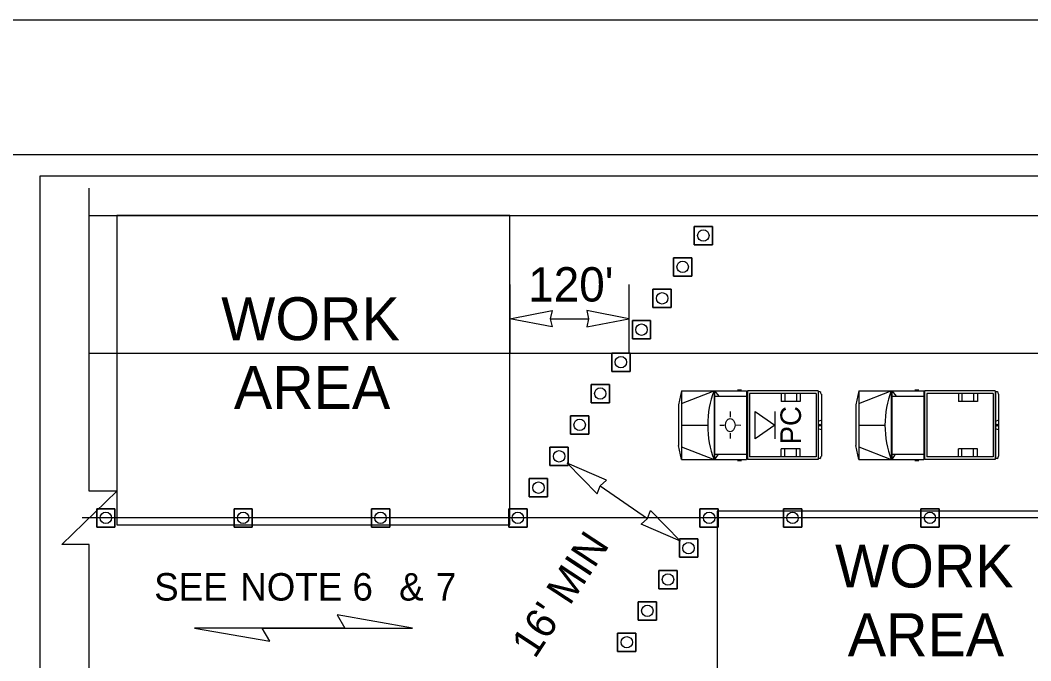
# Model space of a CAD drawing. Extents: x 99999.1 to 100095.7, y 99995 to 100010.7.
# Drawn here: x 100045.223 to 100047.578, y 100009.196 to 100010.687 of the extents above; entities that cross this region are included whole.
import ezdxf

# ---------------------------------------------------------------- set-up
doc = ezdxf.new("R2010")
doc.units = 0
for name, color, linetype in [('RD_ED_ShoulderPavedEdge', 7, 'Continuous'), ('RD_MK_LineEdgeWhite', 7, 'Continuous'), ('RD_MK_LineSkipCenter', 7, 'Continuous'), ('SH_GI_PlotLimits', 7, 'Continuous'), ('SH_GI_SheetBorder', 7, 'Continuous'), ('SH_TI_Tables', 7, 'Continuous'), ('TR_WZ_MotoristVehicle', 7, 'Continuous'), ('TR_WZ_PortableSignMountBlk-Wht', 7, 'Continuous'), ('TR_WZ_TrafficCone', 7, 'Continuous'), ('TR_WZ_WorkAreaLabel', 7, 'Continuous'), ('TR_WZ_WorkZoneDetails', 7, 'Continuous'), ('TR_WZ_WorkZoneTextCurrent', 7, 'Continuous')]:
    doc.layers.add(name, color=color, linetype=linetype)

msp = doc.modelspace()

# ---------------------------------------------------------------- linework, layer by layer
at = {"layer": 'RD_ED_ShoulderPavedEdge'}
msp.add_line((100045.3842, 100010.2323), (100049.3016, 100010.2323), dxfattribs=at)
at = {"layer": 'RD_MK_LineEdgeWhite'}
msp.add_line((100045.3842, 100009.9123), (100049.3016, 100009.9123), dxfattribs=at)
at = {"layer": 'RD_MK_LineSkipCenter'}
msp.add_lwpolyline([(100049.285, 100009.5283), (100045.3677, 100009.5283)], dxfattribs=at)
at = {"layer": 'SH_GI_PlotLimits'}
msp.add_lwpolyline([(100039.0625, 99999.6875), (100056.0625, 99999.6875), (100056.0625, 100010.6875), (100039.0625, 100010.6875)], close=True, dxfattribs=at)
at = {"layer": 'SH_GI_SheetBorder'}
msp.add_line((100040, 100010.375), (100055.75, 100010.375), dxfattribs=at)
at = {"layer": 'SH_TI_Tables'}
msp.add_lwpolyline([(100045.2702, 100010.325), (100050.7241, 100010.325), (100050.7241, 100008.2892), (100045.2702, 100008.2892)], close=True, dxfattribs=at)
at = {"layer": 'TR_WZ_MotoristVehicle'}
for p, q in [((100046.7643, 100009.8243), (100046.7569, 100009.792)), ((100046.7643, 100009.8243), (100046.7643, 100009.6643)), ((100046.7643, 100009.8243), (100046.9154, 100009.8243)), ((100046.7643, 100009.795), (100046.8399, 100009.8243)), ((100046.8399, 100009.8243), (100046.8399, 100009.6643)), ((100046.8412, 100009.8243), (100046.8412, 100009.6643)), ((100046.8412, 100009.8243), (100046.8509, 100009.8119)), ((100046.8412, 100009.8119), (100046.9154, 100009.8119)), ((100046.8948, 100009.8266), (100046.9039, 100009.8266)), ((100046.9154, 100009.8243), (100046.9154, 100009.6643)), ((100047.0822, 100009.8243), (100046.9176, 100009.8243)), ((100046.9176, 100009.8243), (100046.9176, 100009.6643)), ((100047.0775, 100009.8179), (100046.9223, 100009.8179)), ((100046.9223, 100009.8179), (100046.9223, 100009.6707)), ((100046.9965, 100009.8179), (100046.9965, 100009.7995)), ((100047.0045, 100009.8179), (100047.0045, 100009.7995)), ((100047.0317, 100009.8179), (100047.0317, 100009.7995)), ((100047.0404, 100009.8179), (100047.0404, 100009.7995)), ((100047.0775, 100009.8179), (100047.0775, 100009.6707)), ((100047.0822, 100009.8243), (100047.0822, 100009.6643)), ((100047.0863, 100009.8217), (100047.0828, 100009.8217)), ((100047.0828, 100009.8217), (100047.0828, 100009.667)), ((100047.0899, 100009.8168), (100047.0899, 100009.6718)), ((100047.1773, 100009.8243), (100047.1699, 100009.792)), ((100047.1773, 100009.8243), (100047.1773, 100009.6643)), ((100047.1773, 100009.8243), (100047.3284, 100009.8243)), ((100047.1773, 100009.795), (100047.2529, 100009.8243)), ((100047.2529, 100009.8243), (100047.2529, 100009.6643)), ((100047.2543, 100009.8243), (100047.2543, 100009.6643)), ((100047.2543, 100009.8243), (100047.2639, 100009.8119)), ((100047.2543, 100009.8119), (100047.3284, 100009.8119)), ((100047.3078, 100009.8266), (100047.3169, 100009.8266)), ((100047.3284, 100009.8243), (100047.3284, 100009.6643)), ((100047.4952, 100009.8243), (100047.3306, 100009.8243)), ((100047.3306, 100009.8243), (100047.3306, 100009.6643)), ((100047.4905, 100009.8179), (100047.3353, 100009.8179)), ((100047.3353, 100009.8179), (100047.3353, 100009.6707)), ((100047.4095, 100009.8179), (100047.4095, 100009.7995)), ((100047.4175, 100009.8179), (100047.4175, 100009.7995)), ((100047.4447, 100009.8179), (100047.4447, 100009.7995)), ((100047.4535, 100009.8179), (100047.4535, 100009.7995)), ((100047.4905, 100009.8179), (100047.4905, 100009.6707)), ((100047.4952, 100009.8243), (100047.4952, 100009.6643)), ((100047.4993, 100009.8217), (100047.4958, 100009.8217)), ((100047.4958, 100009.8217), (100047.4958, 100009.667)), ((100047.5029, 100009.8168), (100047.5029, 100009.6718)), ((100046.7569, 100009.792), (100046.7569, 100009.6966)), ((100047.0404, 100009.7995), (100046.9965, 100009.7995)), ((100047.1699, 100009.792), (100047.1699, 100009.6966)), ((100047.4535, 100009.7995), (100047.4095, 100009.7995)), ((100046.8775, 100009.776), (100046.8775, 100009.7631)), ((100046.7643, 100009.7443), (100046.825, 100009.7443)), ((100046.8534, 100009.7444), (100046.8635, 100009.7444)), ((100046.8888, 100009.7441), (100046.8888, 100009.7441)), ((100046.9022, 100009.7437), (100046.8903, 100009.744)), ((100047.0899, 100009.7556), (100047.0828, 100009.7526)), ((100047.0899, 100009.7331), (100047.0828, 100009.7361)), ((100047.088, 100009.7443), (100047.0847, 100009.7443)), ((100047.0863, 100009.7466), (100047.0863, 100009.7421)), ((100047.1773, 100009.7443), (100047.238, 100009.7443)), ((100047.5029, 100009.7556), (100047.4958, 100009.7526)), ((100047.5029, 100009.7331), (100047.4958, 100009.7361)), ((100047.501, 100009.7443), (100047.4977, 100009.7443)), ((100047.4993, 100009.7466), (100047.4993, 100009.7421)), ((100046.8781, 100009.7136), (100046.8779, 100009.7256)), ((100046.7643, 100009.6643), (100046.7569, 100009.6966)), ((100046.7643, 100009.6936), (100046.8399, 100009.6643)), ((100046.9965, 100009.6707), (100046.9965, 100009.6891)), ((100047.0404, 100009.6891), (100046.9965, 100009.6891)), ((100047.0045, 100009.6707), (100047.0045, 100009.6891)), ((100047.0317, 100009.6707), (100047.0317, 100009.6891)), ((100047.0404, 100009.6707), (100047.0404, 100009.6891)), ((100047.1773, 100009.6643), (100047.1699, 100009.6966)), ((100047.1773, 100009.6936), (100047.2529, 100009.6643)), ((100047.4095, 100009.6707), (100047.4095, 100009.6891)), ((100047.4535, 100009.6891), (100047.4095, 100009.6891)), ((100047.4175, 100009.6707), (100047.4175, 100009.6891)), ((100047.4447, 100009.6707), (100047.4447, 100009.6891)), ((100047.4535, 100009.6707), (100047.4535, 100009.6891)), ((100046.8412, 100009.6767), (100046.9154, 100009.6767)), ((100046.8492, 100009.6767), (100046.8412, 100009.6643)), ((100047.0775, 100009.6707), (100046.9223, 100009.6707)), ((100047.0863, 100009.667), (100047.0828, 100009.667)), ((100047.2543, 100009.6767), (100047.3284, 100009.6767)), ((100047.2622, 100009.6767), (100047.2543, 100009.6643)), ((100047.4905, 100009.6707), (100047.3353, 100009.6707)), ((100047.4993, 100009.667), (100047.4958, 100009.667)), ((100046.7643, 100009.6643), (100046.9154, 100009.6643)), ((100046.8948, 100009.6621), (100046.9039, 100009.6621)), ((100047.0822, 100009.6643), (100046.9176, 100009.6643)), ((100047.1773, 100009.6643), (100047.3284, 100009.6643)), ((100047.3078, 100009.6621), (100047.3169, 100009.6621)), ((100047.4952, 100009.6643), (100047.3306, 100009.6643))]:
    msp.add_line(p, q, dxfattribs=at)
for centre, major_axis, start_param, end_param in [((100046.9479, 100009.7443), (0, -0.1679), 4.215667, 5.208926), ((100047.0863, 100009.8168), (0, 0.00488), 4.712389, 6.283185), ((100047.3609, 100009.7443), (0, -0.1679), 4.215667, 5.208926), ((100047.4993, 100009.8168), (0, 0.00488), 4.712389, 6.283185), ((100047.0863, 100009.6718), (0, -0.00488), 0, 1.570796), ((100047.4993, 100009.6718), (0, -0.00488), 0, 1.570796)]:
    msp.add_ellipse(centre, major_axis=major_axis, ratio=0.73155, start_param=start_param, end_param=end_param, dxfattribs=at)
for centre, major_axis in [((100046.8775, 100009.7443), (0, 0.0154)), ((100047.0863, 100009.7443), (0, 0.00225)), ((100047.4993, 100009.7443), (0, 0.00225))]:
    msp.add_ellipse(centre, major_axis=major_axis, ratio=0.73155, dxfattribs=at)
at = {"layer": 'TR_WZ_PortableSignMountBlk-Wht'}
msp.add_line((100046.9814, 100009.7763), (100046.9814, 100009.7123), dxfattribs=at)
msp.add_lwpolyline([(100046.9814, 100009.7443), (100046.9354, 100009.7123), (100046.9354, 100009.7763)], close=True, dxfattribs=at)
at = {"layer": 'TR_WZ_TrafficCone'}
for points in [[(100046.7936, 100010.2073), (100046.8362, 100010.2073), (100046.8362, 100010.1646), (100046.7936, 100010.1646), (100046.7936, 100010.2073)], [(100046.7936, 100010.1646), (100046.8362, 100010.1646), (100046.8362, 100010.2073), (100046.7936, 100010.2073), (100046.7936, 100010.1646)], [(100046.7456, 100010.1342), (100046.7882, 100010.1342), (100046.7882, 100010.0915), (100046.7456, 100010.0915), (100046.7456, 100010.1342)], [(100046.7456, 100010.0915), (100046.7882, 100010.0915), (100046.7882, 100010.1342), (100046.7456, 100010.1342), (100046.7456, 100010.0915)], [(100046.6976, 100010.0611), (100046.7402, 100010.0611), (100046.7402, 100010.0185), (100046.6976, 100010.0185), (100046.6976, 100010.0611)], [(100046.6976, 100010.0185), (100046.7402, 100010.0185), (100046.7402, 100010.0611), (100046.6976, 100010.0611), (100046.6976, 100010.0185)], [(100046.6496, 100009.9881), (100046.6922, 100009.9881), (100046.6922, 100009.9454), (100046.6496, 100009.9454), (100046.6496, 100009.9881)], [(100046.6496, 100009.9454), (100046.6922, 100009.9454), (100046.6922, 100009.9881), (100046.6496, 100009.9881), (100046.6496, 100009.9454)], [(100046.6442, 100009.9123), (100046.6015, 100009.9123), (100046.6015, 100009.8697), (100046.6442, 100009.8697), (100046.6442, 100009.9123)], [(100046.6442, 100009.8697), (100046.6015, 100009.8697), (100046.6015, 100009.9123), (100046.6442, 100009.9123), (100046.6442, 100009.8697)], [(100046.5962, 100009.8393), (100046.5535, 100009.8393), (100046.5535, 100009.7966), (100046.5962, 100009.7966), (100046.5962, 100009.8393)], [(100046.5962, 100009.7966), (100046.5535, 100009.7966), (100046.5535, 100009.8393), (100046.5962, 100009.8393), (100046.5962, 100009.7966)], [(100046.5482, 100009.7662), (100046.5055, 100009.7662), (100046.5055, 100009.7235), (100046.5482, 100009.7235), (100046.5482, 100009.7662)], [(100046.5482, 100009.7235), (100046.5055, 100009.7235), (100046.5055, 100009.7662), (100046.5482, 100009.7662), (100046.5482, 100009.7235)], [(100046.5002, 100009.6931), (100046.4575, 100009.6931), (100046.4575, 100009.6505), (100046.5002, 100009.6505), (100046.5002, 100009.6931)], [(100046.5002, 100009.6505), (100046.4575, 100009.6505), (100046.4575, 100009.6931), (100046.5002, 100009.6931), (100046.5002, 100009.6505)], [(100046.4522, 100009.6201), (100046.4095, 100009.6201), (100046.4095, 100009.5774), (100046.4522, 100009.5774), (100046.4522, 100009.6201)], [(100046.4522, 100009.5774), (100046.4095, 100009.5774), (100046.4095, 100009.6201), (100046.4522, 100009.6201), (100046.4522, 100009.5774)], [(100045.4016, 100009.5497), (100045.4442, 100009.5497), (100045.4442, 100009.507), (100045.4016, 100009.507), (100045.4016, 100009.5497)], [(100045.4016, 100009.507), (100045.4442, 100009.507), (100045.4442, 100009.5497), (100045.4016, 100009.5497), (100045.4016, 100009.507)], [(100045.7216, 100009.5497), (100045.7642, 100009.5497), (100045.7642, 100009.507), (100045.7216, 100009.507), (100045.7216, 100009.5497)], [(100045.7216, 100009.507), (100045.7642, 100009.507), (100045.7642, 100009.5497), (100045.7216, 100009.5497), (100045.7216, 100009.507)], [(100046.0416, 100009.5497), (100046.0842, 100009.5497), (100046.0842, 100009.507), (100046.0416, 100009.507), (100046.0416, 100009.5497)], [(100046.0416, 100009.507), (100046.0842, 100009.507), (100046.0842, 100009.5497), (100046.0416, 100009.5497), (100046.0416, 100009.507)], [(100046.4042, 100009.5497), (100046.3615, 100009.5497), (100046.3615, 100009.507), (100046.4042, 100009.507), (100046.4042, 100009.5497)], [(100046.4042, 100009.507), (100046.3615, 100009.507), (100046.3615, 100009.5497), (100046.4042, 100009.5497), (100046.4042, 100009.507)], [(100046.8498, 100009.5497), (100046.8072, 100009.5497), (100046.8072, 100009.507), (100046.8498, 100009.507), (100046.8498, 100009.5497)], [(100046.8498, 100009.507), (100046.8072, 100009.507), (100046.8072, 100009.5497), (100046.8498, 100009.5497), (100046.8498, 100009.507)], [(100047.0016, 100009.5497), (100047.0442, 100009.5497), (100047.0442, 100009.507), (100047.0016, 100009.507), (100047.0016, 100009.5497)], [(100047.0016, 100009.507), (100047.0442, 100009.507), (100047.0442, 100009.5497), (100047.0016, 100009.5497), (100047.0016, 100009.507)], [(100047.3216, 100009.5497), (100047.3642, 100009.5497), (100047.3642, 100009.507), (100047.3216, 100009.507), (100047.3216, 100009.5497)], [(100047.3216, 100009.507), (100047.3642, 100009.507), (100047.3642, 100009.5497), (100047.3216, 100009.5497), (100047.3216, 100009.507)], [(100046.7592, 100009.4366), (100046.8019, 100009.4366), (100046.8019, 100009.4793), (100046.7592, 100009.4793), (100046.7592, 100009.4366)], [(100046.7592, 100009.4793), (100046.8019, 100009.4793), (100046.8019, 100009.4366), (100046.7592, 100009.4366), (100046.7592, 100009.4793)], [(100046.7112, 100009.3635), (100046.7539, 100009.3635), (100046.7539, 100009.4062), (100046.7112, 100009.4062), (100046.7112, 100009.3635)], [(100046.7112, 100009.4062), (100046.7539, 100009.4062), (100046.7539, 100009.3635), (100046.7112, 100009.3635), (100046.7112, 100009.4062)], [(100046.6632, 100009.2905), (100046.7059, 100009.2905), (100046.7059, 100009.3331), (100046.6632, 100009.3331), (100046.6632, 100009.2905)], [(100046.6632, 100009.3331), (100046.7059, 100009.3331), (100046.7059, 100009.2905), (100046.6632, 100009.2905), (100046.6632, 100009.3331)], [(100046.6152, 100009.2174), (100046.6579, 100009.2174), (100046.6579, 100009.2601), (100046.6152, 100009.2601), (100046.6152, 100009.2174)], [(100046.6152, 100009.2601), (100046.6579, 100009.2601), (100046.6579, 100009.2174), (100046.6152, 100009.2174), (100046.6152, 100009.2601)]]:
    msp.add_lwpolyline(points, dxfattribs=at)
for centre in [(100046.8149, 100010.1859), (100046.7669, 100010.1129), (100046.7189, 100010.0398), (100046.6709, 100009.9667), (100046.6229, 100009.891), (100046.5749, 100009.8179), (100046.5269, 100009.7449), (100046.4789, 100009.6718), (100046.4309, 100009.5987), (100045.4229, 100009.5283), (100045.7429, 100009.5283), (100046.0629, 100009.5283), (100046.3829, 100009.5283), (100046.8285, 100009.5283), (100047.0229, 100009.5283), (100047.3429, 100009.5283), (100046.7806, 100009.4579), (100046.7326, 100009.3849), (100046.6846, 100009.3118), (100046.6366, 100009.2387)]:
    msp.add_circle(centre, 0.0133, dxfattribs=at)
at = {"layer": 'TR_WZ_WorkZoneDetails'}
for p, q in [((100046.3642, 100010.0723), (100046.3642, 100009.9123)), ((100046.6416, 100010.0723), (100046.6416, 100009.9123)), ((100046.458, 100009.9923), (100046.5478, 100009.9923)), ((100046.5748, 100009.6027), (100046.6847, 100009.5271)), ((100045.787, 100009.2718), (100045.9799, 100009.2718)), ((100045.9799, 100009.2718), (100045.787, 100009.2718))]:
    msp.add_line(p, q, dxfattribs=at)
msp.add_lwpolyline([(100045.3842, 100008.7603), (100045.3842, 100009.4664), (100045.3202, 100009.4664), (100045.4483, 100009.5903), (100045.3842, 100009.5903), (100045.3842, 100010.2963)], dxfattribs=at)
for points in [[(100045.4483, 100010.2323), (100045.4483, 100009.5123), (100046.3642, 100009.5123), (100046.3642, 100010.2323)], [(100046.3642, 100009.9923), (100046.4625, 100010.0116), (100046.458, 100009.9923), (100046.4625, 100009.9731)], [(100046.6416, 100009.9923), (100046.5433, 100010.0116), (100046.5478, 100009.9923), (100046.5433, 100009.9731)], [(100046.4976, 100009.6558), (100046.5676, 100009.5842), (100046.5748, 100009.6027), (100046.5895, 100009.616)], [(100046.7619, 100009.4739), (100046.67, 100009.5138), (100046.6847, 100009.5271), (100046.6918, 100009.5455)], [(100046.8472, 100009.5443), (100046.8472, 100009.1443), (100047.8256, 100009.1443), (100047.8256, 100009.5443)], [(100046.1371, 100009.2718), (100045.962, 100009.3026), (100045.9799, 100009.2718)], [(100045.6298, 100009.2718), (100045.8048, 100009.2409), (100045.787, 100009.2718)]]:
    msp.add_lwpolyline(points, close=True, dxfattribs=at)

# ---------------------------------------------------------------- texts
at = {"layer": 'TR_WZ_MotoristVehicle'}
msp.add_text('PC', height=0.048, rotation=90, dxfattribs=at).set_placement((100047.0425, 100009.6995))
at = {"layer": 'TR_WZ_WorkAreaLabel'}
for s, p in [('WORK', (100045.6917, 100009.9423)), ('AREA', (100045.7214, 100009.7823)), ('WORK', (100047.1219, 100009.3663)), ('AREA', (100047.1515, 100009.2063))]:
    msp.add_text(s, height=0.1, dxfattribs=at).set_placement(p)
at = {"layer": 'TR_WZ_WorkZoneTextCurrent'}
for s, height, rotation, p in [("120'", 0.08, 360, (100046.4068, 100010.0323)), ("16' MIN", 0.07, 56.6977, (100046.4224, 100009.1982))]:
    msp.add_text(s, height=height, rotation=rotation, dxfattribs=at).set_placement(p)
for s, p in [('SEE', (100045.5355, 100009.3358)), ('NOTE 6', (100045.736, 100009.3358)), ('&', (100046.1062, 100009.3358)), ('7', (100046.1919, 100009.3358))]:
    msp.add_text(s, height=0.064, dxfattribs=at).set_placement(p)

doc.saveas('drawing.dxf')
